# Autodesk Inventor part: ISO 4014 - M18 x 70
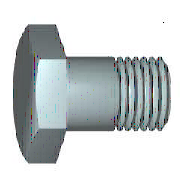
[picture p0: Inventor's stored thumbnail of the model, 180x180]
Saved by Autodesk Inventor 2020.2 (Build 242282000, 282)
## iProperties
Manager: www.cadconsulting.pl
Company: Fabian Stasiak CAD Consulting
IsCustomPart: 0
Created: 2016-02
Part Number: ISO 4014 - M18 x 70
Material: Stal nierdzewna 440C
Description: Śruba z łbem sześciokątnym - Klasa dokładności A i B
Document SubType Name: Modeling
Standard: ISO 4014
Designer: F.Stasiak
Standard Revision: Fourth edition 2011-03-15
Standards Organization: ISO
Language: pl-PL
Size Designation: M18 x 70
Categories: <MemberInstance><Categories><Category DisplayName="Mocowania" InternalName="e4da775c-781d-43d5-af7c-5136215cf5a6" Mnemonic="FSTN"><Category DisplayName="Śruby"
Density: 7.75 g/cm^3
Appearance: Częściowo polerowana
Author: F.Stasiak
Subject: Zbiór ćwiczeń. Autodesk Inventor 2020. Kurs podstawowy
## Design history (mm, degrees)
sketch "Szkic1"
  geometry: L1 (0, 12.67)-(0, 9); L2 (28, 9)-(70, 9); L3 (70, 9)-(70, 0); L4 (70, 0)-(-0.8, 0); L5 (-14.96, 0)-(84.16, 0) reference; L6 (-0.8, 0)-(-0.8, 12.67); L7 (-0.8, 12.67)-(0, 12.67); L8 (28, 9)-(26.466, 9); L9 (26.466, 9)-(0, 9); L10 (0, -2.534)-(0, 15.204) reference
  constraints: 16 end point, 2 collinear, 2 perpendicular, 1 parallel
  dimensions: "d0" = 70 distance between parallel lines of L3 L1 (= NLG); "d1" = 42 distance from line of L2.start L3 (= GEL); "d2" = 18 diameter of L2 L4 (= GD); "d9" = 0.8001 distance between parallel lines of L6 L1 (computed from SD); "d10" = 25.34 diameter of L7 L4 (= SD2); "d13" = 1.53373 distance of L2.start L8.end (computed from GAL); "d14" = 18 diameter of L9 L4 (= BDM)
revolve "Bryła" sketch "Szkic1" stored, may be unused: angle "d12" = 90 deg
sketch "Szkic2"
  geometry: L1 (0, 15.588)-(13.5, 7.794); L2 (13.5, 7.794)-(13.5, -7.794); L3 (13.5, -7.794)-(0, -15.588); L4 (0, -15.588)-(-13.5, -7.794); L5 (-13.5, -7.794)-(-13.5, 7.794); L6 (-13.5, 7.794)-(0, 15.588); 2 further points
  constraints: 12 end point, 1 coincident, 1 vertical, 11 other
  dimensions: "d11" = 27 distance between parallel lines of L5 L2 (= SW)
extrude "Głowica" join sketch "Szkic2" distance "d3" = 10.7 (= KOH - SD); taper "d4" = 0 deg
sketch "Szkic4"
  geometry: L1 (-11.5, 13.5)-(-11.5, 15.588); L2 (-11.5, 15.588)-(-10.294, 15.588); L3 (-10.294, 15.588)-(-11.5, 13.5); L4 (-13.64, 0)-(1.34, 0) reference; L5 (-0.8, 15.588)-(-11.5, 15.588) reference; L6 (-11.5, 7.794)-(-11.5, 15.588) reference
  constraints: 6 end point, 2 collinear, 1 perpendicular, 1 vertical
  dimensions: "d5" = 30 deg angle of L3 L1 (= ANG1); "d19" = 27 diameter of L1.start L4 (= SW0)
revolve "Faza1" sketch "Szkic4" stored, may be unused: angle "d21" = 90 deg
workplane "Work Plane1"
body "Solid1"
feature "Gwint" dims "d15" = 42 (= GEL), "d16" = 0
chamfer "Faza2" distance "d6" = 1.53362 (= -0.5 x SPD + 0.5 x GD); stored, may be unused: second distance "d7" = 1.53373 (computed from GUL), angle "d55" = 45 deg
other parameters: "NLG" = 70 [user parameter; used in 1 equation term], "GD" = 18 (= NND) [user parameter; used in 2 equation terms], "BDM" = 18 (= NND) [user parameter; used in 1 equation term], "KOH" = 11.5 [user parameter; used in 1 equation term], "GEL" = 42 [user parameter; used in 2 equation terms], "SW" = 27 [user parameter; used in 3 equation terms], "SW0" = 27 (= SW) [user parameter; used in 1 equation term], "SPD" = 14.93275 (= NND - 1.2269 x PTC) [user parameter; used in 1 equation term], "SD2" = 25.34 [user parameter; used in 2 equation terms], "SD" = 0.8 [user parameter; used in 2 equation terms], "ANG1" = 30 deg [user parameter; used in 1 equation term], "GAL" = 1.53363 (= 0.61345 x PTC) [user parameter; used in 1 equation term], "GUL" = 1.53363 (= 0.61345 x PTC) [user parameter; used in 1 equation term], "d8" = 0, "RR" = 0.6 [user parameter], "d57" = 0, "d58" = 0, "TPU" = 4 (computed from PTC) [user parameter], "GD1" = 14.93275 (= THREADDIA - 1.2269 x PTC) [user parameter], "THREADDIA" = 18 [user parameter; used in 1 equation term], "SDH" = 25.34 (= SD2) [user parameter], "TOA" = 30 deg [user parameter], "PTC" = 2.5 [user parameter; used in 5 equation terms], "NND" = 18 [user parameter; used in 3 equation terms], "E0" = 31.185 (= 1.155 x SW) [user parameter]
